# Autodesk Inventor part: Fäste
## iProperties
Created: 2001-12
Part Number: Fäste
Material: S235JRG2
Document SubType Name: Modeling
Designer: Tobben
Control State: 0
Master: False
Checked Out: False
Shininess: 64.0
Length Units: 11269
Angle Units: 11279
Time Units: 11290
Mass Units: 11283
Length Display Precision: 3
Angle Display Precision: 2
Compacted: True
Density: 0.0
Volumn: 0.0
Area: 0.0
PropertySet Name: Model Information
Author: Tobben
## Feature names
1. Extrusion1
2. Extrusion2
3. Extrusion3
4. Extrusion4
5. Hole1
6. Hole2
